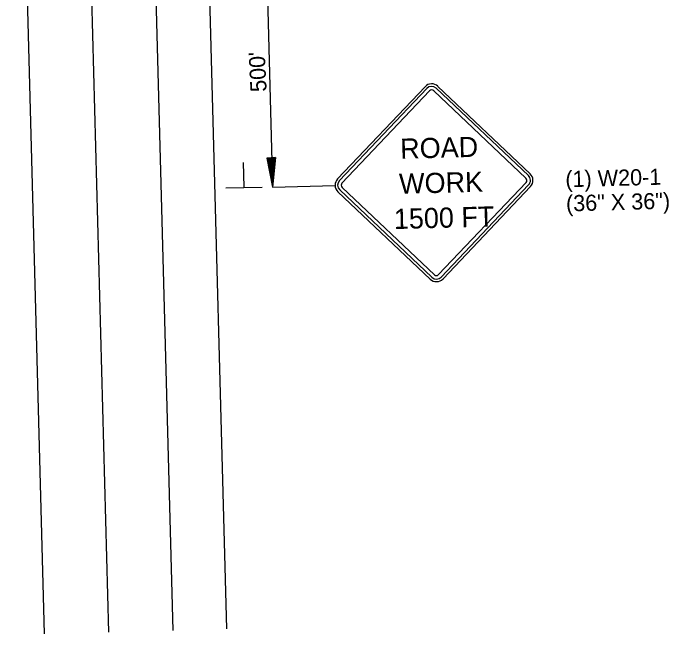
# Model space of a CAD drawing. Extents: x 1929653 to 1931621, y 596452 to 600944.
# Drawn here: x 1930830.4 to 1931074.1, y 599672.3 to 599903.1 of the extents above; entities that cross this region are included whole.
import ezdxf

# ---------------------------------------------------------------- set-up
doc = ezdxf.new("R2010")
doc.units = 0
for name, color, linetype in [('P_TC_Signs_Temporary', 7, 'Continuous'), ('R_Border', 7, 'Continuous'), ('R_Draft', 7, 'Continuous')]:
    doc.layers.add(name, color=color, linetype=linetype)

msp = doc.modelspace()

# ---------------------------------------------------------------- linework, layer by layer
at = {"layer": 'P_TC_Signs_Temporary'}
for p, q in [((1930951, 599841.42), (1930983.5, 599875.71)), ((1930987.63, 599875.16), (1931021.92, 599842.66)), ((1930988.27, 599875.84), (1931022.57, 599843.34)), ((1930951.68, 599840.77), (1930984.18, 599875.07)), ((1930952.63, 599839.87), (1930985.13, 599874.17)), ((1930986.72, 599874.21), (1931021.02, 599841.71)), ((1931021.06, 599840.12), (1930988.56, 599805.82)), ((1931022.01, 599839.21), (1930989.51, 599804.92)), ((1931022.69, 599838.57), (1930990.19, 599804.27)), ((1930985.42, 599804.15), (1930951.13, 599836.65)), ((1930986.07, 599804.83), (1930951.77, 599837.33)), ((1930986.97, 599805.78), (1930952.67, 599838.28))]:
    msp.add_line(p, q, dxfattribs=at)
for centre, radius, start, end in [((1930985.95, 599873.39), 3.38, 46.5377, 136.5377), ((1930985.95, 599873.39), 2.44, 46.5377, 136.5377), ((1930985.95, 599873.39), 1.13, 46.5377, 136.5377), ((1930953.45, 599839.1), 3.38, 136.5377, 226.5377), ((1931020.24, 599840.89), 1.12, 316.5377, 46.5377), ((1931020.24, 599840.89), 2.44, 316.5377, 46.5377), ((1931020.24, 599840.89), 3.38, 316.5377, 46.5377), ((1930953.45, 599839.1), 2.44, 136.5377, 226.5377), ((1930953.45, 599839.1), 1.12, 136.5377, 226.5377), ((1930987.74, 599806.6), 2.44, 226.5377, 316.5377), ((1930987.74, 599806.6), 1.13, 226.5377, 316.5377), ((1930987.74, 599806.6), 3.38, 226.5377, 316.5377)]:
    msp.add_arc(centre, radius, start, end, dxfattribs=at)
at = {"layer": 'R_Draft'}
for p, q in [((1930865.96, 599672.89), (1930854.32, 600106.75)), ((1930889.89, 599673.54), (1930878.25, 600107.39)), ((1930909.83, 599674.07), (1930898.19, 600107.92)), ((1930842.03, 599672.25), (1930830.39, 600106.1)), ((1930924.1, 599938.35), (1930926.81, 599838.5)), ((1930927.95, 599849.32), (1930924.69, 599849.18)), ((1930924.69, 599849.18), (1930926.79, 599838.38)), ((1930924.96, 599849.2), (1930926.71, 599840.2)), ((1930925.24, 599849.21), (1930926.63, 599842.06)), ((1930925.51, 599849.22), (1930926.55, 599843.88)), ((1930925.79, 599849.23), (1930926.47, 599845.72)), ((1930926.06, 599849.24), (1930926.39, 599847.54)), ((1930926.57, 599849.27), (1930926.39, 599847.54)), ((1930926.85, 599849.27), (1930926.47, 599845.72)), ((1930927.13, 599849.28), (1930926.55, 599843.88)), ((1930927.4, 599849.3), (1930926.63, 599842.06)), ((1930927.68, 599849.31), (1930926.71, 599840.2)), ((1930927.95, 599849.32), (1930926.79, 599838.38)), ((1930916.23, 599838.29), (1930915.98, 599847.48)), ((1930926.79, 599838.38), (1930950.07, 599839.01)), ((1930922.94, 599838.28), (1930909.47, 599837.92))]:
    msp.add_line(p, q, dxfattribs=at)

# ---------------------------------------------------------------- texts
at = {"layer": 'P_TC_Signs_Temporary'}
for s, p in [(' ROAD ', (1930971.58, 599848.8)), ('WORK', (1930973.96, 599835.84)), ('1500 FT', (1930972.01, 599822.76))]:
    msp.add_text(s, height=7.5, rotation=1.5377, dxfattribs=at).set_placement(p)
at = {"layer": 'R_Border'}
for s, p in [('(1) W20-1', (1931035.74, 599838.31)), ('(36" X 36")', (1931035.98, 599829.31))]:
    msp.add_text(s, height=6, rotation=1.5377, dxfattribs=at).set_placement(p)
at = {"layer": 'R_Draft'}
msp.add_text("500'", height=6, rotation=92.7681, dxfattribs=at).set_placement((1930924.64, 599873.92))

doc.saveas('drawing.dxf')
